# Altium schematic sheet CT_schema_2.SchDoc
size 572 x 279 mm
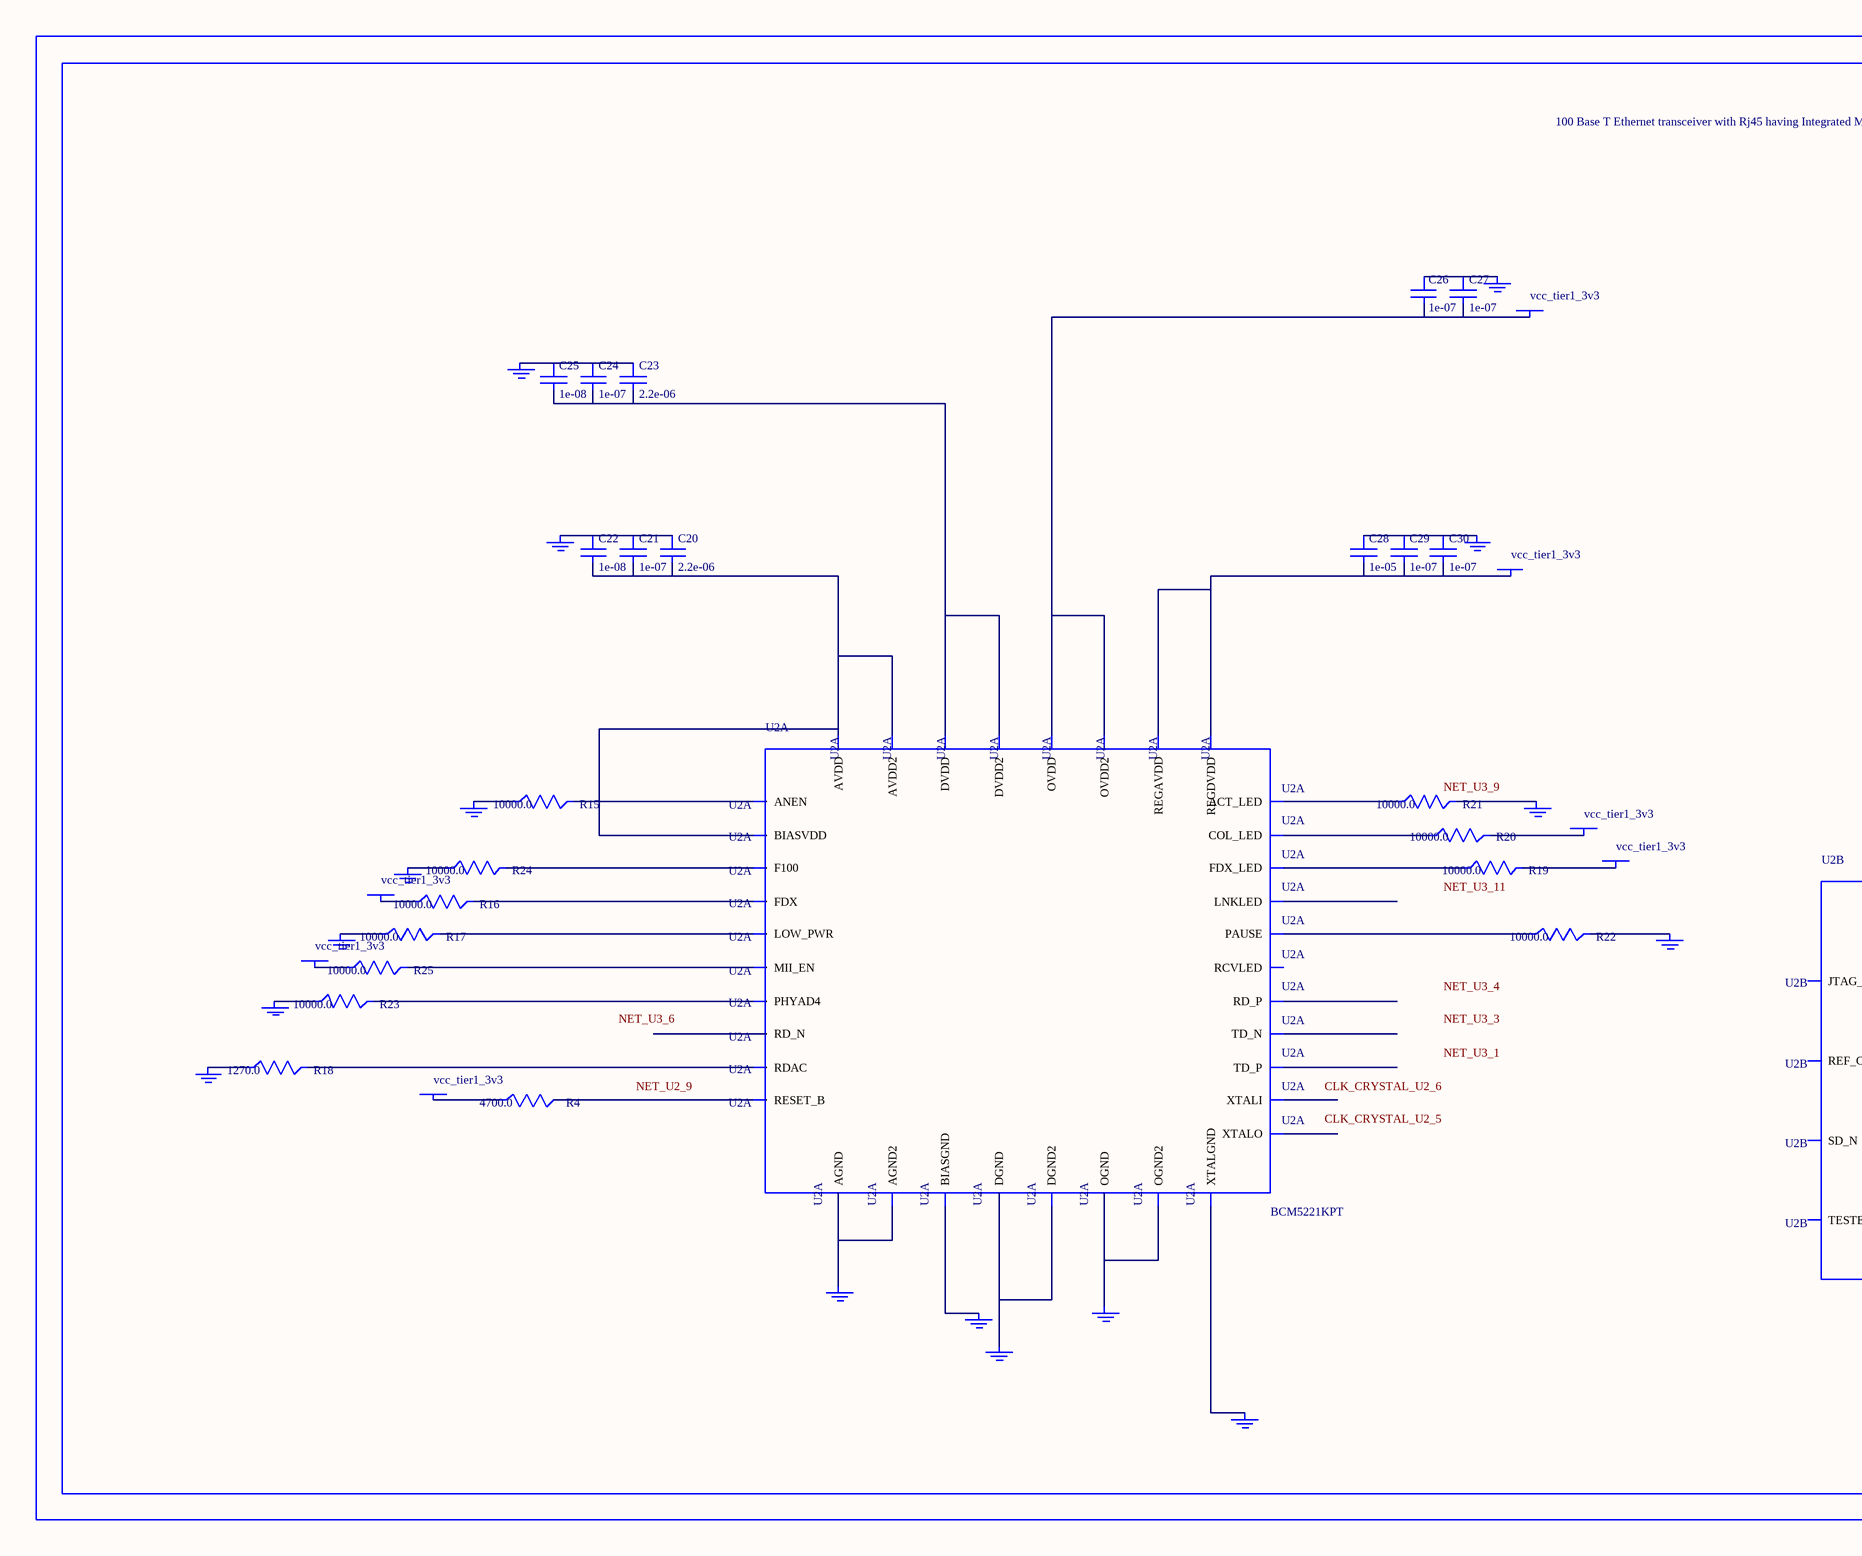
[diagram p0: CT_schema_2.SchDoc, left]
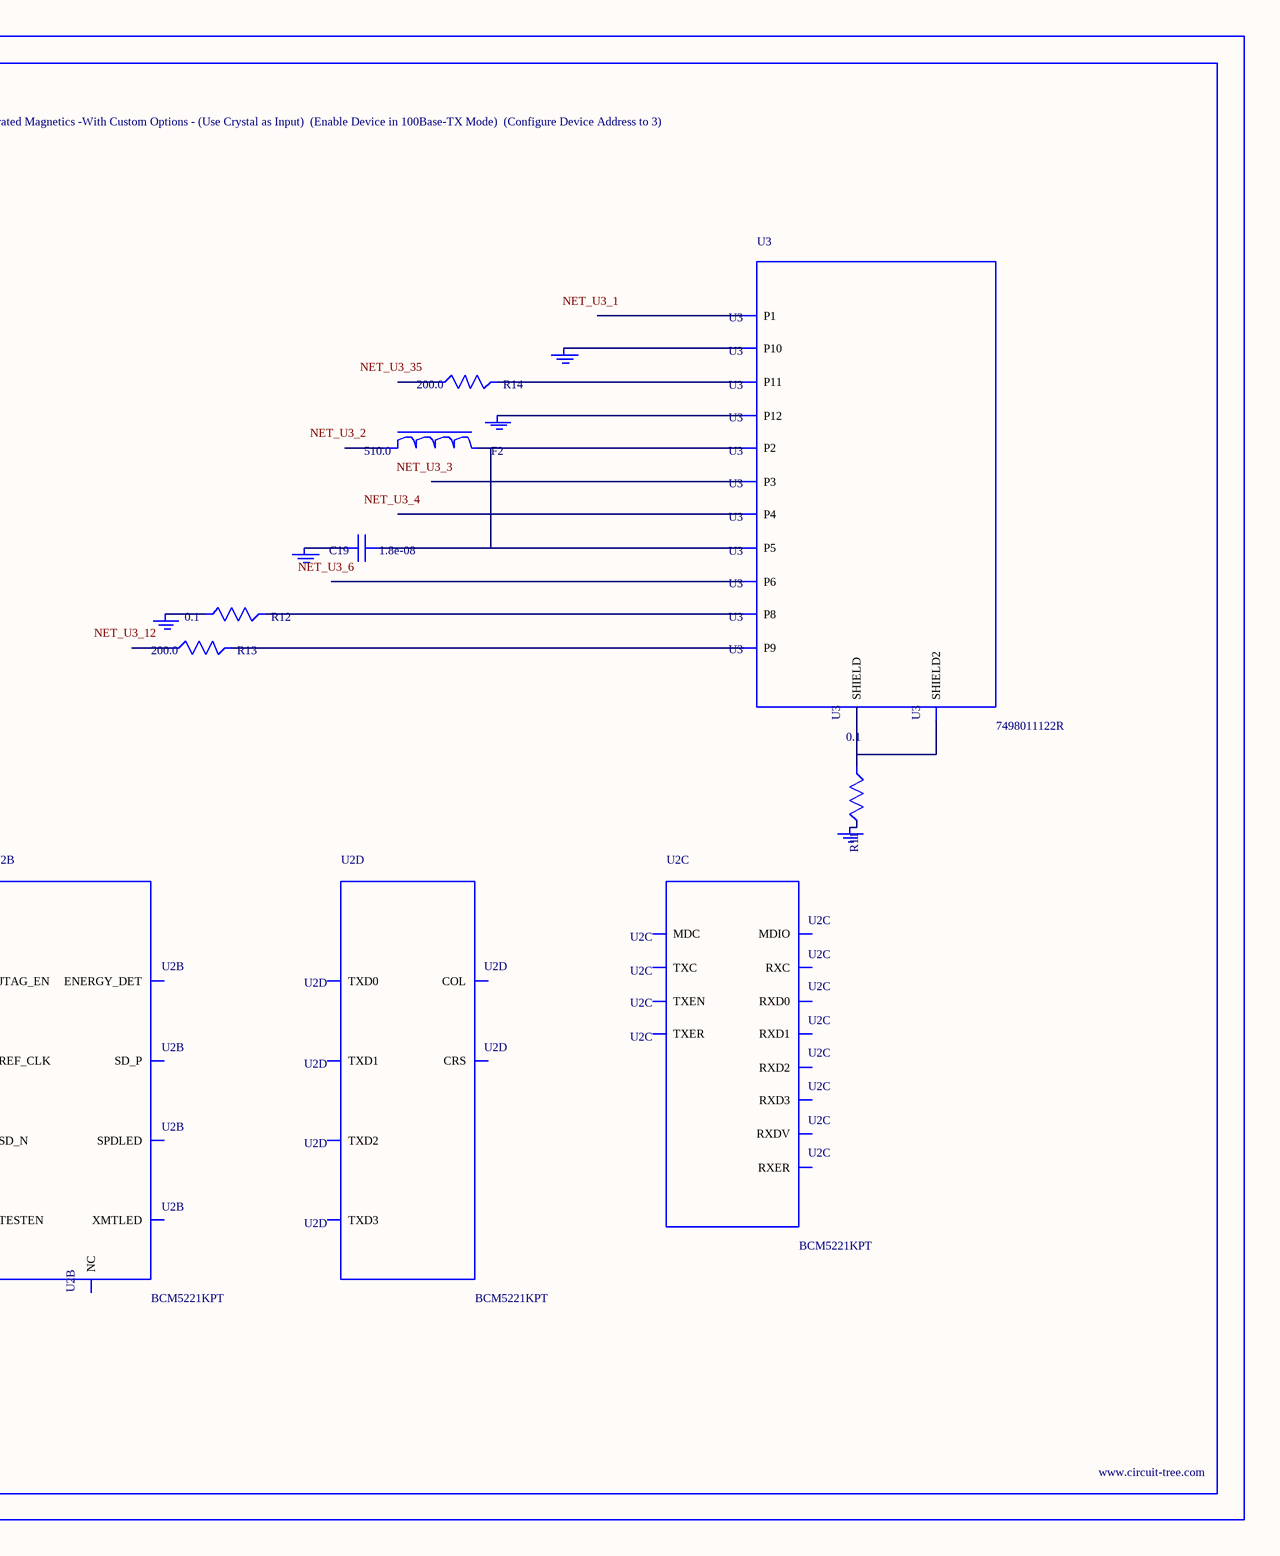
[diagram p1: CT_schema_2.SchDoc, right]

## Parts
BORDER1  (no value)
C19  1.8e-08  [C0402]
C20  2.2e-06  [C0603]
C21  1e-07  [C0402]
C22  1e-08  [C0402]
C23  2.2e-06  [C0603]
C24  1e-07  [C0402]
C25  1e-08  [C0402]
C26  1e-07  [C0402]
C27  1e-07  [C0402]
C28  1e-05  [C0805]
C29  1e-07  [C0402]
C30  1e-07  [C0402]
F2  510.0  [L0603]
GND_INSTANCE_1_0  (no value)
GND_INSTANCE_1_1  (no value)
GND_INSTANCE_1_2  (no value)
GND_INSTANCE_1_3  (no value)
GND_INSTANCE_1_4  (no value)
GND_INSTANCE_1_5  (no value)
GND_INSTANCE_1_6  (no value)
GND_INSTANCE_1_7  (no value)
GND_INSTANCE_1_8  (no value)
GND_INSTANCE_1_9  (no value)
GND_INSTANCE_1_10  (no value)
GND_INSTANCE_1_11  (no value)
GND_INSTANCE_1_12  (no value)
GND_INSTANCE_1_13  (no value)
GND_INSTANCE_1_14  (no value)
GND_INSTANCE_1_15  (no value)
GND_INSTANCE_1_16  (no value)
GND_INSTANCE_1_17  (no value)
GND_INSTANCE_1_18  (no value)
GND_INSTANCE_1_19  (no value)
GND_INSTANCE_1_20  (no value)
POWER_INSTANCE_1_0  vcc_tier1_3v3
POWER_INSTANCE_1_1  vcc_tier1_3v3
POWER_INSTANCE_1_2  vcc_tier1_3v3
POWER_INSTANCE_1_3  vcc_tier1_3v3
POWER_INSTANCE_1_4  vcc_tier1_3v3
POWER_INSTANCE_1_5  vcc_tier1_3v3
POWER_INSTANCE_1_6  vcc_tier1_3v3
R4  4700.0  [R0603]
R11  0.1  [R0603]
R12  0.1  [R0603]
R13  200.0  [R0603]
R14  200.0  [R0603]
R15  10000.0  [R0603]
R16  10000.0  [R0603]
R17  10000.0  [R0603]
R18  1270.0  [R0603]
R19  10000.0  [R0603]
R20  10000.0  [R0603]
R21  10000.0  [R0603]
R22  10000.0  [R0603]
R23  10000.0  [R0603]
R24  10000.0  [R0603]
R25  10000.0  [R0603]
U2  BCM5221KPT  [TQFP64_10X10MC]  (parts A,B,C,D of 4)
U3  7498011122R  [7498011122R]

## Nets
NetC19_1: C19.1 F2.2 U3.2(P2) U3.5(P5)
NetC19_2: C19.2 GND_INSTANCE_1_16.0(GND)
NetC20_1: C20.1 C21.1 C22.1 GND_INSTANCE_1_10.0(GND)
NetC20_2: C20.2 C21.2 C22.2 U2.22(BIASVDD) U2.27(AVDD) U2.28(AVDD2)
NetC23_1: C23.1 C24.1 C25.1 GND_INSTANCE_1_1.0(GND)
NetC23_2: C23.2 C24.2 C25.2 U2.2(DVDD) U2.55(DVDD2)
NetC26_1: C26.1 C27.1 GND_INSTANCE_1_0.0(GND)
NetC26_2: C26.2 C27.2 POWER_INSTANCE_1_0.0(PWR) U2.1(OVDD) U2.46(OVDD2)
NetC28_1: C28.1 C29.1 C30.1 GND_INSTANCE_1_2.0(GND)
NetC28_2: C28.2 C29.2 C30.2 POWER_INSTANCE_1_1.0(PWR) U2.3(REGDVDD) U2.20(REGAVDD)
NetGND_INSTANCE_1_3_0: GND_INSTANCE_1_3.0(GND) U2.7(XTALGND)
NetGND_INSTANCE_1_4_0: GND_INSTANCE_1_4.0(GND) R21.2
NetGND_INSTANCE_1_5_0: GND_INSTANCE_1_5.0(GND) R22.2
NetGND_INSTANCE_1_6_0: GND_INSTANCE_1_6.0(GND) R23.1
NetGND_INSTANCE_1_7_0: GND_INSTANCE_1_7.0(GND) R17.1
NetGND_INSTANCE_1_8_0: GND_INSTANCE_1_8.0(GND) R18.1
NetGND_INSTANCE_1_9_0: GND_INSTANCE_1_9.0(GND) U2.24(BIASGND)
NetGND_INSTANCE_1_11_0: GND_INSTANCE_1_11.0(GND) R24.1
NetGND_INSTANCE_1_12_0: GND_INSTANCE_1_12.0(GND) R15.1
NetGND_INSTANCE_1_13_0: GND_INSTANCE_1_13.0(GND) U2.29(AGND) U2.32(AGND2)
NetGND_INSTANCE_1_14_0: GND_INSTANCE_1_14.0(GND) U2.40(OGND) U2.45(OGND2)
NetGND_INSTANCE_1_15_0: GND_INSTANCE_1_15.0(GND) U2.54(DGND) U2.63(DGND2)
NetGND_INSTANCE_1_17_0: GND_INSTANCE_1_17.0(GND) R12.1
NetGND_INSTANCE_1_18_0: GND_INSTANCE_1_18.0(GND) U3.10(P10)
NetGND_INSTANCE_1_19_0: GND_INSTANCE_1_19.0(GND) U3.12(P12)
NetGND_INSTANCE_1_20_0: GND_INSTANCE_1_20.0(GND) R11.2
NetPOWER_INSTANCE_1_2_0: POWER_INSTANCE_1_2.0(PWR) R19.2
NetPOWER_INSTANCE_1_3_0: POWER_INSTANCE_1_3.0(PWR) R20.2
NetPOWER_INSTANCE_1_4_0: POWER_INSTANCE_1_4.0(PWR) R25.1
NetPOWER_INSTANCE_1_5_0: POWER_INSTANCE_1_5.0(PWR) R16.1
NetPOWER_INSTANCE_1_6_0: POWER_INSTANCE_1_6.0(PWR) R4.1
NetR4_2: R4.2 U2.9(RESET_B)
NetR11_1: R11.1 U3.13(SHIELD) U3.14(SHIELD2)
NetR12_2: R12.2 U3.8(P8)
NetR13_2: R13.2 U3.9(P9)
NetR14_2: R14.2 U3.11(P11)
NetR15_2: R15.2 U2.38(ANEN)
NetR16_2: R16.2 U2.39(FDX)
NetR17_2: R17.2 U2.16(LOW_PWR)
NetR18_2: R18.2 U2.23(RDAC)
NetR19_1: R19.1 U2.10(FDX_LED)
NetR20_1: R20.1 U2.11(COL_LED)
NetR21_1: R21.1 U2.12(ACT_LED)
NetR22_1: R22.1 U2.13(PAUSE)
NetR23_2: R23.2 U2.14(PHYAD4)
NetR24_2: R24.2 U2.37(F100)
NetR25_2: R25.2 U2.18(MII_EN)

Not connected (* = marked no-connect by the designer): F2 1; R13 1; R14 1; U2 4(REF_CLK) 5(XTALO) 6(XTALI) 8(NC) 15(TESTEN) 17(ENERGY_DET) 19(SD_N) 21(SD_P) 25(RD_N) 26(RD_P) 30(TD_N) 31(TD_P) 33(RCVLED) 34(XMTLED) 35(LNKLED) 36(SPDLED) 41(MDIO) 42(MDC) 43(RXD3) 44(RXD2) 47(RXD1) 48(RXD0) 49(RXDV) 50(RXC) 51(RXER) 52(TXER) 53(TXC) 56(TXEN) 57(TXD0) 58(TXD1) 59(TXD2) 60(TXD3) 61(COL) 62(CRS) 64(JTAG_EN); U3 1(P1) 3(P3) 4(P4) 6(P6)

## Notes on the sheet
- Labels drawn without touching a wire or pin: CLK_CRYSTAL_U2_5, CLK_CRYSTAL_U2_6, NET_U2_9, NET_U3_1, NET_U3_2, NET_U3_3, NET_U3_4, NET_U3_6, NET_U3_9, NET_U3_11, NET_U3_12, NET_U3_35

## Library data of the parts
BORDER1 = BORDER_PAGE1
C19 = C0402C183K3RAC
C20 C23 = C0603C225K8RACTU
C21 C24 C26 C27 C29 C30 = C0402C104K3RACTU
C22 C25 = C0402C103K3RAC
C28 = C0805C106K8RACTU
F2 = ERA3APB511V
GND_INSTANCE_1_0-GND_INSTANCE_1_20 = GND
POWER_INSTANCE_1_0-POWER_INSTANCE_1_6 = PWR
R4 = RC0603JR-074K7L
R11 R12 = ERJ-3RSFR10V
R13 R14 = RC0603JR-07200RL
R15-R17 R19-R25 = RC0603JR-0710KL
R18 = RC0603FR-071K27L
